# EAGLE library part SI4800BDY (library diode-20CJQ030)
Vishay Siliconix N-Channel Reduced Qg, Fast Switching MOSFET FEATURES: TrenchFET Power MOSFET High-Efficient PWM Optimized 100% UIS Tested Please send any comments to: messi@users.sourceforge.net
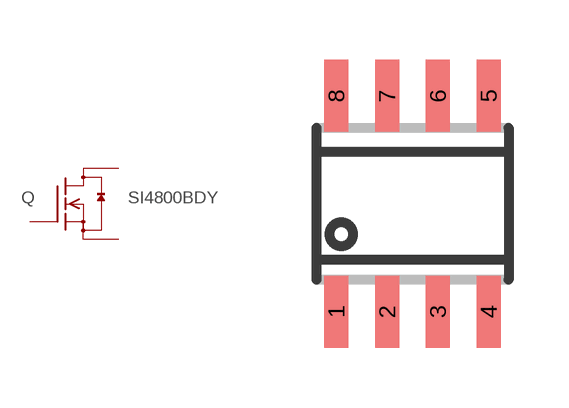
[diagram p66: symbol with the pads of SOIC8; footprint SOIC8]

Designator prefix Q

## SI4800BDY  [SOIC8]
1  S  pas
2  S  pas
3  S  pas
4  G  pas
5  D  pas
6  D  pas
7  D  pas
8  D  pas

## Footprint SOIC8 (pad centres in mm)
Small Outline IC
smd 0.6 x 1.8: 1 -1.905,-2.7; 2 -0.635,-2.7; 3 0.635,-2.7; 4 1.905,-2.7; 5 1.905,2.7; 6 0.635,2.7; 7 -0.635,2.7; 8 -1.905,2.7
